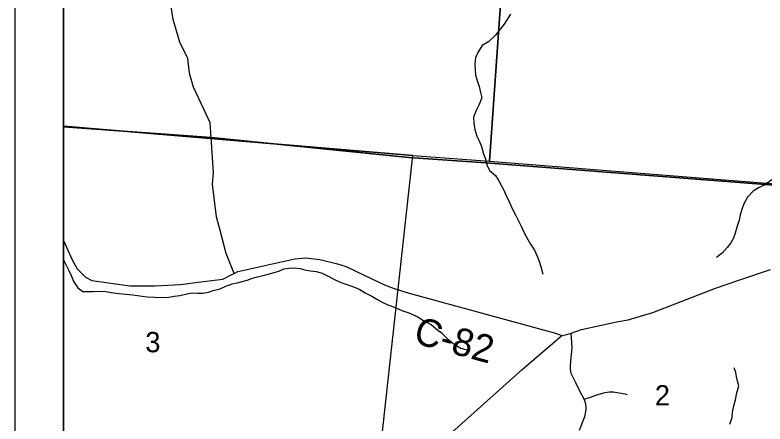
# Model space of a CAD drawing. Extents: x 0 to 34, y 0 to 22.
# Drawn here: x 23.417 to 24.965, y 19.535 to 20.378 of the extents above; entities that cross this region are included whole.
import ezdxf

# ---------------------------------------------------------------- set-up
doc = ezdxf.new("R2010")
doc.units = 0
for name, color, linetype in [('GM_X_Corporation', 7, 'Continuous'), ('GM_X_County_Road', 7, 'Continuous'), ('GM_X_County_Road_Text', 7, 'Continuous'), ('GM_X_Minor_River', 7, 'Continuous'), ('GM_X_Section_Text', 7, 'Continuous'), ('GM_X_Township_Road', 7, 'Continuous'), ('SH_Data', 7, 'Continuous')]:
    doc.layers.add(name, color=color, linetype=linetype)

msp = doc.modelspace()

# ---------------------------------------------------------------- linework, layer by layer
at = {"layer": 'GM_X_Corporation'}
for points in [[(24.4541, 20.9), (23.5167, 20.9), (23.5167, 20.1488), (24.2381, 20.0885), (24.3968, 20.0768)], [(26.3743, 20.9), (23.5167, 20.9), (23.5167, 20.1476), (23.8215, 20.1257), (24.2296, 20.084), (24.3889, 20.0736), (25.117, 20.0172), (25.2916, 20.0037), (25.482, 19.99), (25.7174, 19.9778), (26.3029, 19.931), (26.3351, 20.3683)], [(25.3573, 20.9), (24.4541, 20.9), (24.3968, 20.0768), (25.2979, 20.0049)], [(23.5167, 20.1488), (23.5167, 19.3154), (24.147, 19.2629), (24.2381, 20.0885)], [(24.3968, 20.0768), (25.2979, 20.0049), (25.2286, 19.1118), (24.145, 19.219), (24.147, 19.2629), (24.2381, 20.0885)]]:
    msp.add_lwpolyline(points, close=True, dxfattribs=at)
msp.add_lwpolyline([(26.1825, 18.4635), (26.1926, 18.5708), (26.207, 18.8068), (26.2271, 19.0168), (26.2277, 19.0233), (26.2281, 19.0286), (26.3029, 19.931), (25.7174, 19.9778), (25.482, 19.99), (25.2916, 20.0037), (25.117, 20.0172), (24.3889, 20.0736), (24.2296, 20.084), (23.8215, 20.1257), (23.5167, 20.1476), (23.5167, 14.1), (25.8273, 14.1), (25.8671, 14.5774), (25.9626, 15.7291)], dxfattribs=at)
at = {"layer": 'GM_X_County_Road'}
for points in [[(23.5167, 19.9134), (23.5338, 19.8747), (23.5453, 19.8549), (23.5624, 19.8373), (23.575, 19.8307), (23.6537, 19.8197), (23.7059, 19.8197), (23.7581, 19.8224), (23.8005, 19.8279), (23.8455, 19.8331), (23.8619, 19.8414), (23.869, 19.8452), (23.8765, 19.849), (23.9946, 19.8752), (24.0172, 19.8774), (24.0463, 19.8741), (24.0826, 19.8648), (24.1002, 19.8593), (24.1233, 19.8488), (24.1799, 19.8217), (24.1996, 19.814), (24.2306, 19.8047), (24.5326, 19.7223), (24.546, 19.7172), (24.556, 19.7191), (24.5652, 19.7222), (24.5865, 19.7292), (24.6243, 19.7381), (24.6587, 19.7451), (24.6828, 19.7493), (24.7336, 19.7647), (24.863, 19.8149), (24.9132, 19.832), (24.9766, 19.8534)], [(24.5824, 19.5222), (24.5895, 19.5398), (24.5933, 19.55), (24.5948, 19.5566), (24.5958, 19.5655), (24.5959, 19.5693), (24.5952, 19.5761), (24.5934, 19.5825), (24.5917, 19.5861), (24.5826, 19.6039), (24.5751, 19.6185), (24.5704, 19.6277), (24.5676, 19.6331), (24.5653, 19.6386), (24.5641, 19.6431), (24.5635, 19.6481), (24.5636, 19.6536), (24.5646, 19.6652), (24.5662, 19.6845), (24.5669, 19.6924), (24.566, 19.7123), (24.5652, 19.7222)]]:
    msp.add_lwpolyline(points, dxfattribs=at)
at = {"layer": 'GM_X_Minor_River'}
for points in [[(24.4397, 20.3798), (24.4267, 20.3594), (24.4187, 20.3492), (24.4088, 20.3364), (24.3947, 20.3228), (24.381, 20.3153), (24.3722, 20.301), (24.3676, 20.2896), (24.366, 20.2768), (24.3666, 20.2646), (24.3677, 20.2544), (24.3714, 20.2407), (24.3751, 20.2308), (24.3781, 20.2186), (24.3803, 20.2073), (24.3741, 20.1925), (24.3687, 20.1815), (24.3637, 20.1675), (24.3644, 20.155), (24.3662, 20.1417), (24.3703, 20.1284), (24.3751, 20.1185), (24.38, 20.1068), (24.3836, 20.0942), (24.3881, 20.0805), (24.3918, 20.0676), (24.3966, 20.0577), (24.4087, 20.047), (24.4154, 20.0364), (24.4259, 20.0166), (24.4304, 20.0071), (24.4371, 19.9926), (24.4445, 19.9766), (24.4501, 19.9663), (24.4565, 19.9534), (24.4621, 19.9427), (24.4684, 19.9275), (24.4759, 19.9153), (24.4811, 19.9058), (24.4894, 19.8929), (24.4946, 19.8811), (24.4998, 19.8685), (24.5031, 19.8568), (24.5068, 19.8435)], [(24.9796, 20.0383), (24.9648, 20.0282), (24.953, 20.0222), (24.9412, 20.0147), (24.9294, 20.0026), (24.9214, 19.989), (24.9179, 19.9792), (24.914, 19.9659), (24.9117, 19.9553), (24.9078, 19.9425), (24.9039, 19.9285), (24.9005, 19.9182), (24.8951, 19.9084), (24.8875, 19.8986), (24.8768, 19.8869), (24.8654, 19.8779)], [(23.5167, 19.8735), (23.5231, 19.861), (23.5276, 19.8511), (23.5328, 19.8409), (23.538, 19.8275), (23.5462, 19.8154), (23.5568, 19.8081), (23.5685, 19.8076), (23.5787, 19.8079), (23.5905, 19.8086), (23.6045, 19.8078), (23.6151, 19.8058), (23.6309, 19.8038), (23.6445, 19.8022), (23.6597, 19.8013), (23.6695, 19.7994), (23.6793, 19.7982), (23.6899, 19.7969), (23.705, 19.7961), (23.7206, 19.7952), (23.7342, 19.7963), (23.7452, 19.7981), (23.7573, 19.7999), (23.7721, 19.8032), (23.7827, 19.805), (23.7936, 19.8046), (23.8042, 19.8045), (23.8164, 19.8067), (23.8258, 19.8097), (23.8402, 19.8134), (23.852, 19.819), (23.8653, 19.8238), (23.8755, 19.8257), (23.8854, 19.8283), (23.8964, 19.8316), (23.9074, 19.8353), (23.9176, 19.8379), (23.929, 19.8409), (23.9396, 19.8434), (23.9517, 19.8468), (23.9616, 19.8497), (23.9718, 19.8546), (23.9828, 19.8561), (23.9927, 19.8567), (24.0055, 19.8555), (24.0153, 19.8528), (24.0259, 19.8508), (24.0384, 19.8489), (24.0509, 19.8457), (24.0607, 19.8411), (24.078, 19.8323), (24.0916, 19.8257), (24.1059, 19.8211), (24.118, 19.8168), (24.1286, 19.8122), (24.1399, 19.8053), (24.1535, 19.798), (24.1636, 19.7919), (24.1765, 19.7854), (24.1866, 19.7807), (24.2002, 19.7753), (24.2153, 19.7688), (24.2297, 19.7638), (24.247, 19.7561), (24.2625, 19.7469), (24.276, 19.7399), (24.2866, 19.7308), (24.2971, 19.7227), (24.3106, 19.7097), (24.3234, 19.6994), (24.3374, 19.691), (24.3506, 19.6875)], [(24.8926, 19.5341), (24.8972, 19.5481), (24.8984, 19.5587), (24.9008, 19.572), (24.9043, 19.5848), (24.9074, 19.5989), (24.9113, 19.6136), (24.9072, 19.6284), (24.905, 19.641), (24.9017, 19.6505)]]:
    msp.add_lwpolyline(points, dxfattribs=at)
at = {"layer": 'GM_X_Township_Road'}
for points in [[(23.7763, 20.2646), (23.7733, 20.2883), (23.757, 20.3219), (23.7436, 20.369), (23.7392, 20.3956), (23.753, 20.4312), (23.7809, 20.4925), (23.8167, 20.6004), (23.8405, 20.6629), (23.8638, 20.7102), (23.8929, 20.7707), (23.9117, 20.812), (23.9209, 20.8336), (23.9376, 20.8494), (23.9449, 20.8525)], [(23.869, 19.8452), (23.8527, 19.8862), (23.8406, 19.9335), (23.8324, 19.9621), (23.8247, 20.0293), (23.8263, 20.0529), (23.8217, 20.1252), (23.8198, 20.1557), (23.8066, 20.1842), (23.7851, 20.2293), (23.7774, 20.2557), (23.7763, 20.2646)], [(24.1809, 19.1665), (24.1894, 19.1814), (24.1937, 19.1947), (24.1958, 19.2382), (24.1944, 19.2827), (24.1965, 19.3102), (24.2041, 19.3469), (24.2193, 19.3925), (24.2375, 19.4365), (24.267, 19.4677), (24.2924, 19.4939), (24.4633, 19.6463), (24.5313, 19.7046), (24.546, 19.7172)], [(24.5917, 19.5861), (24.607, 19.591), (24.6162, 19.5939), (24.6274, 19.5975), (24.6355, 19.5999), (24.6438, 19.601), (24.6517, 19.6009), (24.6639, 19.5989), (24.6759, 19.5966), (24.6807, 19.5956)]]:
    msp.add_lwpolyline(points, dxfattribs=at)
at = {"layer": 'SH_Data'}
for points in [[(23.4167, 21), (30.4167, 21), (30.4167, 14), (23.4167, 14)], [(23.5167, 20.9), (30.3167, 20.9), (30.3167, 14.1), (23.5167, 14.1)]]:
    msp.add_lwpolyline(points, close=True, dxfattribs=at)

# ---------------------------------------------------------------- texts
at = {"layer": 'GM_X_County_Road_Text'}
msp.add_text('C-82', height=0.05682, rotation=344.7151, dxfattribs=at).set_placement((24.2373, 19.7023))
at = {"layer": 'GM_X_Section_Text'}
for s, p in [('3', (23.6858, 19.6826)), ('2', (24.7379, 19.5729))]:
    msp.add_text(s, height=0.0419, rotation=0, dxfattribs=at).set_placement(p)

doc.saveas('drawing.dxf')
